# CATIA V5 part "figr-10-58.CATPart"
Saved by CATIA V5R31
Part number: Part1
Bounding box of the stored display mesh (mm): x -322.306 to 0, y -118.205 to 88.531, z 0 to 101.949
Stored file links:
  D:\PROJECTS\Project 2021\US EDITION\CATIA V5 6R 2021\Resources\Part Files\c10_catia_v5_6r2021_prt\c10_catia_v5_6r2021_prt\figr-10-58.CATPart
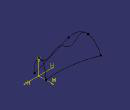
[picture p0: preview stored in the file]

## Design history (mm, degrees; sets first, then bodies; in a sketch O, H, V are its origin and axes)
Set1
  Curve1: Elements (Sketch2.P2; vertex of Sketch1; Sketch3.P2)
Body1 (main body)
  Sketch1 on zx-plane, origin (0, 0, 0), H (-1, 0, 0), V (0, 0, 1)
    spline S1 through (0, 96.336) (70.1946, 72.4244) (144.1119, 96.336) (203.5098, 63.985) (253.668, 92.1163) (322.3056, 72.4244)
    point P1 (0, 96.336)
    coincidence: P1 V
  Sketch2 on xy-plane, origin (0, 0, 0), H (1, 0, 0), V (0, 1, 0)
    point P1 (0, 47.0553)
    point P2 (-315.9706, 88.5306)
    arc A1 centre (-78.7604, 671.3501) radius 629.2433 from (0, 47.0553) to (-315.9706, 88.5306) cw
    coincidence: P1 V
  Sketch3 on xy-plane, origin (0, 0, 0), H (1, 0, 0), V (0, 1, 0)
    line L1 (0, -26.5991) -> (-311.8959, -118.2048)
    point P1 (0, -26.5991)
    point P2 (-311.8959, -118.2048)
    coincidence: P1 V
  Sketch4 on yz-plane, origin (0, 0, 0), H (0, 1, 0), V (0, 0, 1)
    point P1 (-26.5991, 0)
    point P2 (0, 58.544)
    point P3 (47.0553, 0)
    reference projected point E1 (47.0553, 0) from vertex of Sketch2
    reference projected point E2 (-26.5991, 0) from vertex of Sketch3
    spline S1 through (-26.5991, 0) (-29.9268, 35.6209) (0, 96.336) (47.0553, 0)
    reference projected point E3 (0, 96.336) from vertex of Sketch1
    point P4 (-26.5991, 0)
    point P5 (0, 96.336)
    point P6 (47.0553, 0)
    coincidence: P1 H, P3 H, E1 P3, P1 E2, P4 P1, P5 V, P6 P3, E3 S1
